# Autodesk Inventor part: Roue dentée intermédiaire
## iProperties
Author: Flavien MARTY
Shininess: 20.0
PropertySet Name: _Private Model Information
Created: 2001-10
Part Number: Roue dentée intermédiaire
Material: Par défaut
Document SubType Name: Modélisation
Designer: Flavien MARTY
Control State: 0
Master: False
Checked Out: False
PropertySet Name: Design Tracking Control
Density: 0.0
Volumn: 0.0
Area: 0.0
PropertySet Name: Model Information
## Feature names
1. Base1
